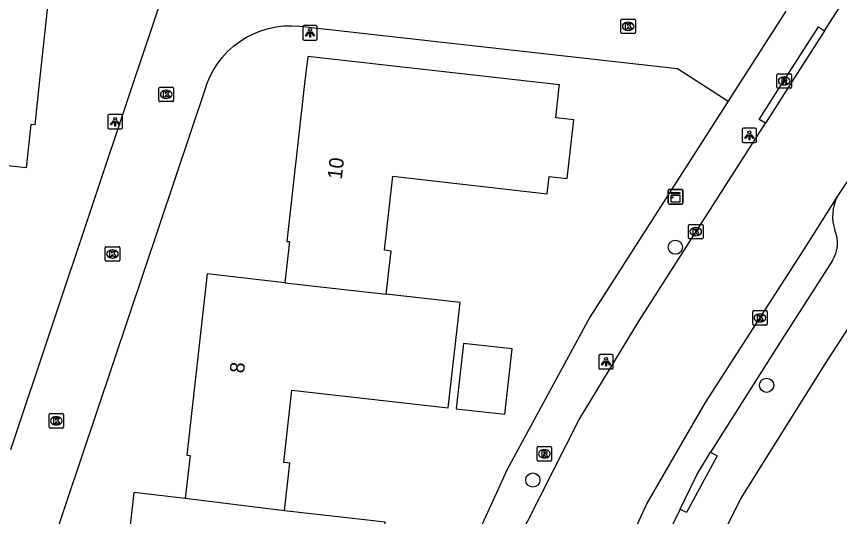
# Model space of a CAD drawing. Extents: x 162398 to 163643, y 386453 to 387397.
# Drawn here: x 162713.1 to 162769.7, y 386720.4 to 386754.8 of the extents above; entities that cross this region are included whole.
import ezdxf

# ---------------------------------------------------------------- set-up
doc = ezdxf.new("R2010")
doc.units = 0
for name, color, linetype in [('IMGEO_Boom', 7, 'Continuous'), ('IMGEO_Kast', 7, 'Continuous'), ('IMGEO_Kolk', 7, 'Continuous'), ('IMGEO_Lichtpunt', 7, 'Continuous'), ('IMGEO_Pand', 7, 'Continuous'), ('IMGEO_Pand_nummerreeks', 7, 'Continuous'), ('IMGEO_Rijbaan_lokaal_open', 7, 'Continuous'), ('IMGEO_Rioolput', 7, 'Continuous'), ('IMGEO_Voetpad_open', 7, 'Continuous')]:
    doc.layers.add(name, color=color, linetype=linetype)

msp = doc.modelspace()

# ---------------------------------------------------------------- linework, layer by layer
at = {"layer": 'IMGEO_Boom'}
for centre in [(162758.414, 386738.944), (162764.691, 386729.444), (162748.609, 386722.92)]:
    msp.add_circle(centre, 0.489, dxfattribs=at)
at = {"layer": 'IMGEO_Kast'}
for p, q in [((162757.926, 386741.989), (162757.926, 386742.83)), ((162757.926, 386742.83), (162757.926, 386741.989)), ((162758.001, 386742.914), (162758.842, 386742.914)), ((162758.842, 386742.914), (162758.001, 386742.914)), ((162758.926, 386742.839), (162758.926, 386741.998)), ((162758.926, 386741.998), (162758.926, 386742.839)), ((162758.851, 386741.914), (162758.01, 386741.914)), ((162758.01, 386741.914), (162758.851, 386741.914))]:
    msp.add_line(p, q, dxfattribs=at)
for points in [[(162758.121, 386742.704), (162758.721, 386742.704), (162758.721, 386742.619), (162758.121, 386742.619), (162758.121, 386742.704)], [(162758.121, 386742.529), (162758.721, 386742.529), (162758.721, 386742.04), (162758.121, 386742.04), (162758.121, 386742.529)]]:
    msp.add_lwpolyline(points, dxfattribs=at)
msp.add_circle((162758.205, 386742.378), 0.0377, dxfattribs=at)
for centre, start, end in [((162758.004, 386742.836), 92.4484, 184.2845), ((162758.004, 386742.836), 92.4484, 184.2845), ((162758.848, 386742.836), 2.4484, 94.2845), ((162758.848, 386742.836), 2.4484, 94.2845), ((162758.004, 386741.992), 182.4484, 274.2845), ((162758.004, 386741.992), 182.4484, 274.2845), ((162758.848, 386741.992), 272.4484, 4.2845), ((162758.848, 386741.992), 272.4484, 4.2845)]:
    msp.add_arc(centre, 0.0779, start, end, dxfattribs=at)
at = {"layer": 'IMGEO_Kolk'}
for p, q in [((162754.669, 386753.716), (162754.669, 386754.568)), ((162754.744, 386754.642), (162755.596, 386754.642)), ((162755.157, 386754.422), (162755.182, 386754.422)), ((162755.67, 386754.568), (162755.67, 386753.716)), ((162755.18, 386753.862), (162755.155, 386753.862)), ((162755.596, 386753.642), (162754.744, 386753.642)), ((162722.894, 386749.034), (162722.894, 386749.886)), ((162722.969, 386749.96), (162723.821, 386749.96)), ((162723.895, 386749.886), (162723.895, 386749.034)), ((162723.382, 386749.74), (162723.407, 386749.74)), ((162723.821, 386748.96), (162722.969, 386748.96)), ((162723.405, 386749.18), (162723.38, 386749.18)), ((162759.317, 386739.588), (162759.317, 386740.44)), ((162759.392, 386740.514), (162760.244, 386740.514)), ((162759.805, 386740.294), (162759.83, 386740.294)), ((162760.318, 386740.44), (162760.318, 386739.588)), ((162759.828, 386739.734), (162759.803, 386739.734)), ((162760.244, 386739.514), (162759.392, 386739.514)), ((162719.193, 386738.055), (162719.193, 386738.907)), ((162719.268, 386738.981), (162720.12, 386738.981)), ((162719.681, 386738.761), (162719.706, 386738.761)), ((162720.194, 386738.907), (162720.194, 386738.055)), ((162720.12, 386737.981), (162719.268, 386737.981)), ((162719.704, 386738.201), (162719.679, 386738.201)), ((162763.733, 386733.652), (162763.733, 386734.504)), ((162763.808, 386734.578), (162764.66, 386734.578)), ((162764.734, 386734.504), (162764.734, 386733.652)), ((162764.221, 386734.358), (162764.246, 386734.358)), ((162764.66, 386733.578), (162763.808, 386733.578)), ((162764.244, 386733.798), (162764.219, 386733.798)), ((162715.331, 386726.571), (162715.331, 386727.423)), ((162715.406, 386727.497), (162716.258, 386727.497)), ((162715.819, 386727.277), (162715.844, 386727.277)), ((162716.332, 386727.423), (162716.332, 386726.571)), ((162715.842, 386726.717), (162715.817, 386726.717)), ((162716.258, 386726.497), (162715.406, 386726.497))]:
    msp.add_line(p, q, dxfattribs=at)
for points in [[(162754.669, 386753.716), (162754.669, 386754.568)], [(162754.744, 386754.642), (162755.596, 386754.642)], [(162754.99, 386754.342), (162755.113, 386754.342), (162755.113, 386754.191), (162755.243, 386754.342), (162755.407, 386754.342), (162755.261, 386754.191), (162755.414, 386753.942), (162755.262, 386753.942), (162755.177, 386754.106), (162755.113, 386754.039), (162755.113, 386753.942), (162754.99, 386753.942), (162754.99, 386754.342)], [(162755.67, 386754.568), (162755.67, 386753.716)], [(162755.596, 386753.642), (162754.744, 386753.642)], [(162722.894, 386749.034), (162722.894, 386749.886)], [(162722.969, 386749.96), (162723.821, 386749.96)], [(162723.895, 386749.886), (162723.895, 386749.034)], [(162723.215, 386749.66), (162723.338, 386749.66), (162723.338, 386749.509), (162723.468, 386749.66), (162723.632, 386749.66), (162723.486, 386749.509), (162723.639, 386749.26), (162723.487, 386749.26), (162723.402, 386749.424), (162723.338, 386749.357), (162723.338, 386749.26), (162723.215, 386749.26), (162723.215, 386749.66)], [(162723.821, 386748.96), (162722.969, 386748.96)], [(162759.317, 386739.588), (162759.317, 386740.44)], [(162759.392, 386740.514), (162760.244, 386740.514)], [(162759.638, 386740.214), (162759.761, 386740.214), (162759.761, 386740.063), (162759.891, 386740.214), (162760.055, 386740.214), (162759.909, 386740.063), (162760.062, 386739.814), (162759.91, 386739.814), (162759.825, 386739.978), (162759.761, 386739.911), (162759.761, 386739.814), (162759.638, 386739.814), (162759.638, 386740.214)], [(162760.318, 386740.44), (162760.318, 386739.588)], [(162760.244, 386739.514), (162759.392, 386739.514)], [(162719.193, 386738.055), (162719.193, 386738.907)], [(162719.268, 386738.981), (162720.12, 386738.981)], [(162719.514, 386738.681), (162719.637, 386738.681), (162719.637, 386738.53), (162719.767, 386738.681), (162719.931, 386738.681), (162719.785, 386738.53), (162719.938, 386738.281), (162719.786, 386738.281), (162719.701, 386738.445), (162719.637, 386738.378), (162719.637, 386738.281), (162719.514, 386738.281), (162719.514, 386738.681)], [(162720.194, 386738.907), (162720.194, 386738.055)], [(162720.12, 386737.981), (162719.268, 386737.981)], [(162763.733, 386733.652), (162763.733, 386734.504)], [(162763.808, 386734.578), (162764.66, 386734.578)], [(162764.734, 386734.504), (162764.734, 386733.652)], [(162764.054, 386734.278), (162764.177, 386734.278), (162764.177, 386734.127), (162764.307, 386734.278), (162764.471, 386734.278), (162764.325, 386734.127), (162764.478, 386733.878), (162764.326, 386733.878), (162764.241, 386734.042), (162764.177, 386733.975), (162764.177, 386733.878), (162764.054, 386733.878), (162764.054, 386734.278)], [(162764.66, 386733.578), (162763.808, 386733.578)], [(162715.331, 386726.571), (162715.331, 386727.423)], [(162715.406, 386727.497), (162716.258, 386727.497)], [(162715.652, 386727.197), (162715.775, 386727.197), (162715.775, 386727.046), (162715.905, 386727.197), (162716.069, 386727.197), (162715.923, 386727.046), (162716.076, 386726.797), (162715.924, 386726.797), (162715.839, 386726.961), (162715.775, 386726.894), (162715.775, 386726.797), (162715.652, 386726.797), (162715.652, 386727.197)], [(162716.332, 386727.423), (162716.332, 386726.571)], [(162716.258, 386726.497), (162715.406, 386726.497)]]:
    msp.add_lwpolyline(points, dxfattribs=at)
for centre, start, end in [((162754.746, 386754.566), 91.552, 178.448), ((162754.746, 386754.566), 91.552, 178.448), ((162755.594, 386754.566), 1.552, 88.448), ((162755.594, 386754.566), 1.552, 88.448), ((162754.746, 386753.718), 181.552, 268.448), ((162754.746, 386753.718), 181.552, 268.448), ((162755.594, 386753.718), 271.552, 358.448), ((162755.594, 386753.718), 271.552, 358.448), ((162722.971, 386749.884), 91.552, 178.448), ((162722.971, 386749.884), 91.552, 178.448), ((162723.819, 386749.884), 1.552, 88.448), ((162723.819, 386749.884), 1.552, 88.448), ((162722.971, 386749.036), 181.552, 268.448), ((162722.971, 386749.036), 181.552, 268.448), ((162723.819, 386749.036), 271.552, 358.448), ((162723.819, 386749.036), 271.552, 358.448), ((162759.394, 386740.438), 91.552, 178.448), ((162759.394, 386740.438), 91.552, 178.448), ((162760.242, 386740.438), 1.552, 88.448), ((162760.242, 386740.438), 1.552, 88.448), ((162759.394, 386739.59), 181.552, 268.448), ((162759.394, 386739.59), 181.552, 268.448), ((162760.242, 386739.59), 271.552, 358.448), ((162760.242, 386739.59), 271.552, 358.448), ((162719.27, 386738.905), 91.552, 178.448), ((162719.27, 386738.905), 91.552, 178.448), ((162720.118, 386738.905), 1.552, 88.448), ((162720.118, 386738.905), 1.552, 88.448), ((162719.27, 386738.057), 181.552, 268.448), ((162719.27, 386738.057), 181.552, 268.448), ((162720.118, 386738.057), 271.552, 358.448), ((162720.118, 386738.057), 271.552, 358.448), ((162763.81, 386734.502), 91.552, 178.448), ((162763.81, 386734.502), 91.552, 178.448), ((162764.658, 386734.502), 1.552, 88.448), ((162764.658, 386734.502), 1.552, 88.448), ((162763.81, 386733.654), 181.552, 268.448), ((162763.81, 386733.654), 181.552, 268.448), ((162764.658, 386733.654), 271.552, 358.448), ((162764.658, 386733.654), 271.552, 358.448), ((162715.408, 386727.421), 91.552, 178.448), ((162715.408, 386727.421), 91.552, 178.448), ((162716.256, 386727.421), 1.552, 88.448), ((162716.256, 386727.421), 1.552, 88.448), ((162715.408, 386726.573), 181.552, 268.448), ((162715.408, 386726.573), 181.552, 268.448), ((162716.256, 386726.573), 271.552, 358.448), ((162716.256, 386726.573), 271.552, 358.448)]:
    msp.add_arc(centre, 0.0765, start, end, dxfattribs=at)
for centre, major_axis, ratio, start_param, end_param in [((162755.156, 386754.142), (-0.387, 0.002), 0.722429, 4.712389, 7.853982), ((162755.181, 386754.142), (-0.39, 0.002), 0.717154, 1.570796, 4.712389), ((162723.381, 386749.46), (-0.387, 0.002), 0.722429, 4.712389, 7.853982), ((162723.406, 386749.46), (-0.39, 0.002), 0.717154, 1.570796, 4.712389), ((162759.804, 386740.014), (-0.387, 0.002), 0.722429, 4.712389, 7.853982), ((162759.829, 386740.014), (-0.39, 0.002), 0.717154, 1.570796, 4.712389), ((162719.68, 386738.481), (-0.387, 0.002), 0.722429, 4.712389, 7.853982), ((162719.705, 386738.481), (-0.39, 0.002), 0.717154, 1.570796, 4.712389), ((162764.22, 386734.078), (-0.387, 0.002), 0.722429, 4.712389, 7.853982), ((162764.245, 386734.078), (-0.39, 0.002), 0.717154, 1.570796, 4.712389), ((162715.818, 386726.997), (-0.387, 0.002), 0.722429, 4.712389, 7.853982), ((162715.843, 386726.997), (-0.39, 0.002), 0.717154, 1.570796, 4.712389)]:
    msp.add_ellipse(centre, major_axis=major_axis, ratio=ratio, start_param=start_param, end_param=end_param, dxfattribs=at)
at = {"layer": 'IMGEO_Lichtpunt'}
for p, q in [((162732.788, 386754.096), (162732.788, 386753.289)), ((162732.788, 386754.096), (162732.788, 386753.289)), ((162733.69, 386754.191), (162732.882, 386754.191)), ((162733.69, 386754.191), (162732.882, 386754.191)), ((162733.784, 386753.289), (162733.784, 386754.096)), ((162733.784, 386753.289), (162733.784, 386754.096)), ((162732.882, 386753.195), (162733.69, 386753.195)), ((162732.882, 386753.195), (162733.69, 386753.195)), ((162720.284, 386748.077), (162719.476, 386748.077)), ((162720.284, 386748.077), (162719.476, 386748.077)), ((162719.382, 386747.982), (162719.382, 386747.175)), ((162719.382, 386747.982), (162719.382, 386747.175)), ((162720.378, 386747.175), (162720.378, 386747.982)), ((162720.378, 386747.175), (162720.378, 386747.982)), ((162719.476, 386747.081), (162720.284, 386747.081)), ((162719.476, 386747.081), (162720.284, 386747.081)), ((162763.004, 386747.044), (162763.004, 386746.237)), ((162763.004, 386747.044), (162763.004, 386746.237)), ((162763.906, 386747.139), (162763.098, 386747.139)), ((162763.906, 386747.139), (162763.098, 386747.139)), ((162764, 386746.237), (162764, 386747.044)), ((162764, 386746.237), (162764, 386747.044)), ((162763.098, 386746.143), (162763.906, 386746.143)), ((162763.098, 386746.143), (162763.906, 386746.143)), ((162753.145, 386731.465), (162753.145, 386730.658)), ((162753.145, 386731.465), (162753.145, 386730.658)), ((162754.047, 386731.56), (162753.239, 386731.56)), ((162754.047, 386731.56), (162753.239, 386731.56)), ((162754.141, 386730.658), (162754.141, 386731.465)), ((162754.141, 386730.658), (162754.141, 386731.465)), ((162753.239, 386730.564), (162754.047, 386730.564)), ((162753.239, 386730.564), (162754.047, 386730.564))]:
    msp.add_line(p, q, dxfattribs=at)
for points in [[(162733.162, 386753.76), (162733.201, 386753.732), (162733.013, 386753.47), (162732.975, 386753.497), (162733.162, 386753.76)], [(162733.374, 386753.732), (162733.412, 386753.759), (162733.599, 386753.497), (162733.56, 386753.469), (162733.374, 386753.732)], [(162733.264, 386753.712), (162733.311, 386753.712), (162733.311, 386753.39), (162733.264, 386753.39), (162733.264, 386753.712)], [(162719.756, 386747.646), (162719.795, 386747.618), (162719.607, 386747.356), (162719.569, 386747.383), (162719.756, 386747.646)], [(162719.858, 386747.598), (162719.905, 386747.598), (162719.905, 386747.276), (162719.858, 386747.276), (162719.858, 386747.598)], [(162719.968, 386747.618), (162720.006, 386747.645), (162720.193, 386747.383), (162720.154, 386747.355), (162719.968, 386747.618)], [(162763.378, 386746.708), (162763.417, 386746.68), (162763.229, 386746.418), (162763.191, 386746.445), (162763.378, 386746.708)], [(162763.48, 386746.66), (162763.527, 386746.66), (162763.527, 386746.338), (162763.48, 386746.338), (162763.48, 386746.66)], [(162763.59, 386746.68), (162763.628, 386746.707), (162763.815, 386746.445), (162763.776, 386746.417), (162763.59, 386746.68)], [(162753.519, 386731.129), (162753.558, 386731.101), (162753.37, 386730.839), (162753.332, 386730.866), (162753.519, 386731.129)], [(162753.731, 386731.101), (162753.769, 386731.128), (162753.956, 386730.866), (162753.917, 386730.838), (162753.731, 386731.101)], [(162753.621, 386731.081), (162753.668, 386731.081), (162753.668, 386730.759), (162753.621, 386730.759), (162753.621, 386731.081)]]:
    msp.add_lwpolyline(points, dxfattribs=at)
for centre in [(162733.287, 386753.894), (162719.881, 386747.78), (162763.503, 386746.842), (162753.644, 386731.263)]:
    msp.add_circle(centre, 0.0994, dxfattribs=at)
for centre, start, end in [((162732.882, 386754.096), 90, 180), ((162732.882, 386754.096), 90, 180), ((162733.69, 386754.096), 0, 90), ((162733.69, 386754.096), 0, 90), ((162732.882, 386753.289), 180, 270), ((162732.882, 386753.289), 180, 270), ((162733.69, 386753.289), 270, 0), ((162733.69, 386753.289), 270, 360), ((162719.476, 386747.982), 90, 180), ((162719.476, 386747.982), 90, 180), ((162720.284, 386747.982), 0, 90), ((162720.284, 386747.982), 0, 90), ((162719.476, 386747.175), 180, 270), ((162719.476, 386747.175), 180, 270), ((162720.284, 386747.175), 270, 0), ((162720.284, 386747.175), 270, 360), ((162763.098, 386747.044), 90, 180), ((162763.098, 386747.044), 90, 180), ((162763.906, 386747.044), 0, 90), ((162763.906, 386747.044), 0, 90), ((162763.098, 386746.237), 180, 270), ((162763.098, 386746.237), 180, 270), ((162763.906, 386746.237), 270, 0), ((162763.906, 386746.237), 270, 360), ((162753.239, 386731.465), 90, 180), ((162753.239, 386731.465), 90, 180), ((162754.047, 386731.465), 0, 90), ((162754.047, 386731.465), 0, 90), ((162753.239, 386730.658), 180, 270), ((162753.239, 386730.658), 180, 270), ((162754.047, 386730.658), 270, 0), ((162754.047, 386730.658), 270, 360)]:
    msp.add_arc(centre, 0.0946, start, end, dxfattribs=at)
at = {"layer": 'IMGEO_Pand'}
for points in [[(162715.694, 386759.778), (162714.638, 386750), (162714.352, 386747.357), (162714.084, 386747.386), (162713.763, 386744.408), (162710.569, 386744.753)], [(162738.531, 386735.719), (162738.865, 386738.683), (162738.398, 386738.736), (162738.971, 386743.824), (162749.594, 386742.626), (162749.727, 386743.807), (162750.979, 386743.666), (162751.435, 386747.704), (162750.183, 386747.845), (162750.426, 386750), (162750.438, 386750.108), (162733.123, 386752.06), (162732.891, 386750), (162731.689, 386739.346), (162731.863, 386739.326), (162731.545, 386736.504)], [(162731.545, 386736.504), (162726.213, 386737.105), (162724.807, 386724.644), (162725.03, 386724.619), (162724.697, 386721.66)], [(162731.545, 386736.504), (162738.531, 386735.719)], [(162731.518, 386720.806), (162731.888, 386724.09), (162731.473, 386724.137), (162732.033, 386729.101), (162742.79, 386727.888), (162743.609, 386735.146), (162738.531, 386735.719)], [(162743.338, 386727.825), (162746.678, 386727.448), (162747.186, 386731.947), (162743.845, 386732.324), (162743.338, 386727.825)], [(162724.697, 386721.66), (162721.171, 386722.057), (162719.763, 386709.572), (162719.989, 386709.546), (162719.653, 386706.562)], [(162731.518, 386720.806), (162724.697, 386721.66)], [(162738.2, 386717.839), (162738.446, 386720.025), (162731.518, 386720.806)]]:
    msp.add_lwpolyline(points, dxfattribs=at)
at = {"layer": 'IMGEO_Rijbaan_lokaal_open'}
for points in [[(162768.682, 386753.831), (162820.766, 386835.256), (162822.004, 386837.173), (162822.433, 386837.832)], [(162712.707, 386725.029), (162721.053, 386750), (162723.976, 386758.744), (162722.022, 386759.421), (162723.941, 386776.08), (162736.827, 386774.61), (162747.949, 386791.857), (162748.421, 386792.667), (162748.819, 386793.516), (162749.139, 386794.397), (162749.38, 386795.303), (162749.538, 386796.228), (162749.557, 386796.385), (162751.861, 386817.275), (162749.46, 386818.878), (162750.034, 386824.476)], [(162766.009, 386755.197), (162762.683, 386750), (162762.044, 386749.001)], [(162710.091, 386702.248), (162726.132, 386750), (162726.172, 386750.119), (162726.376, 386750.623), (162726.624, 386751.108), (162726.914, 386751.568), (162727.244, 386752.001), (162727.611, 386752.402), (162728.013, 386752.769), (162728.446, 386753.099), (162728.907, 386753.389), (162729.392, 386753.636), (162729.896, 386753.839), (162730.417, 386753.996), (162730.95, 386754.106), (162731.491, 386754.168), (162732.035, 386754.181), (162732.578, 386754.146), (162758.569, 386751.236), (162760.491, 386750), (162762.044, 386749.001)], [(162768.682, 386753.831), (162766.226, 386750), (162764.605, 386747.471)], [(162730.673, 386670.035), (162730.769, 386670.321), (162740.68, 386699.903), (162741.907, 386703.446), (162745.663, 386714.324), (162747.378, 386718.341), (162751.779, 386727.044), (162755.937, 386733.921), (162764.605, 386747.471)], [(162769.561, 386742.426), (162771.413, 386745.192)], [(162739.403, 386674.014), (162747.82, 386699.195), (162752.818, 386713.374), (162756.44, 386721.247), (162760.497, 386728.254), (162767.447, 386739.091), (162769.561, 386742.426)]]:
    msp.add_lwpolyline(points, dxfattribs=at)
at = {"layer": 'IMGEO_Rioolput'}
for p, q in [((162765.4, 386749.956), (162765.4, 386750.808)), ((162765.475, 386750.882), (162766.327, 386750.882)), ((162765.888, 386750.662), (162765.913, 386750.662)), ((162766.401, 386750.808), (162766.401, 386749.956)), ((162766.327, 386749.882), (162765.475, 386749.882)), ((162765.911, 386750.102), (162765.886, 386750.102)), ((162748.902, 386724.301), (162748.902, 386725.153)), ((162748.977, 386725.227), (162749.829, 386725.227)), ((162749.39, 386725.007), (162749.415, 386725.007)), ((162749.903, 386725.153), (162749.903, 386724.301)), ((162749.413, 386724.447), (162749.388, 386724.447)), ((162749.829, 386724.227), (162748.977, 386724.227))]:
    msp.add_line(p, q, dxfattribs=at)
for points in [[(162765.4, 386749.956), (162765.4, 386750.808)], [(162765.475, 386750.882), (162766.327, 386750.882)], [(162765.989, 386750.58), (162765.737, 386750.582), (162765.737, 386750.182)], [(162765.737, 386750.182), (162765.861, 386750.182), (162765.861, 386750.344), (162765.872, 386750.344)], [(162765.915, 386750.501), (162765.861, 386750.501), (162765.861, 386750.42)], [(162765.861, 386750.42), (162765.913, 386750.42)], [(162766.401, 386750.808), (162766.401, 386749.956)], [(162766.327, 386749.882), (162765.475, 386749.882)], [(162765.919, 386750.315), (162765.99, 386750.182), (162766.13, 386750.182), (162766.065, 386750.308)], [(162748.902, 386724.301), (162748.902, 386725.153)], [(162748.977, 386725.227), (162749.829, 386725.227)], [(162749.491, 386724.925), (162749.239, 386724.927), (162749.239, 386724.527)], [(162749.903, 386725.153), (162749.903, 386724.301)], [(162749.239, 386724.527), (162749.363, 386724.527), (162749.363, 386724.689), (162749.374, 386724.689)], [(162749.417, 386724.846), (162749.363, 386724.846), (162749.363, 386724.765)], [(162749.363, 386724.765), (162749.415, 386724.765)], [(162749.421, 386724.66), (162749.492, 386724.527), (162749.632, 386724.527), (162749.567, 386724.653)], [(162749.829, 386724.227), (162748.977, 386724.227)]]:
    msp.add_lwpolyline(points, dxfattribs=at)
for centre, radius, start, end in [((162765.477, 386750.806), 0.0765, 91.552, 178.448), ((162765.477, 386750.806), 0.0765, 91.552, 178.448), ((162765.871, 386750.291), 0.0533, 26.0293, 88.6989), ((162765.897, 386750.609), 0.19, 274.7715, 282.9687), ((162765.921, 386750.405), 0.0964, 77.0061, 93.1865), ((162765.935, 386750.462), 0.0378, 276.6634, 79.6772), ((162765.988, 386750.47), 0.109, 350.3612, 89.416), ((162765.986, 386750.47), 0.112, 277.5842, 350.9817), ((162765.97, 386750.255), 0.108, 29.5134, 73.7905), ((162766.325, 386750.806), 0.0765, 1.552, 88.448), ((162766.325, 386750.806), 0.0765, 1.552, 88.448), ((162765.477, 386749.958), 0.0765, 181.552, 268.448), ((162765.477, 386749.958), 0.0765, 181.552, 268.448), ((162766.325, 386749.958), 0.0765, 271.552, 358.448), ((162766.325, 386749.958), 0.0765, 271.552, 358.448), ((162748.979, 386725.151), 0.0765, 91.552, 178.448), ((162748.979, 386725.151), 0.0765, 91.552, 178.448), ((162749.49, 386724.815), 0.109, 350.3612, 89.416), ((162749.827, 386725.151), 0.0765, 1.552, 88.448), ((162749.827, 386725.151), 0.0765, 1.552, 88.448), ((162748.979, 386724.303), 0.0765, 181.552, 268.448), ((162748.979, 386724.303), 0.0765, 181.552, 268.448), ((162749.373, 386724.636), 0.0533, 26.0293, 88.6989), ((162749.399, 386724.954), 0.19, 274.7715, 282.9687), ((162749.423, 386724.75), 0.0964, 77.0061, 93.1865), ((162749.437, 386724.807), 0.0378, 276.6634, 79.6772), ((162749.488, 386724.815), 0.112, 277.5842, 350.9817), ((162749.472, 386724.6), 0.108, 29.5134, 73.7905), ((162749.827, 386724.303), 0.0765, 271.552, 358.448), ((162749.827, 386724.303), 0.0765, 271.552, 358.448)]:
    msp.add_arc(centre, radius, start, end, dxfattribs=at)
for centre, major_axis, ratio, start_param, end_param in [((162765.887, 386750.382), (-0.387, 0.002), 0.722429, 4.712389, 7.853982), ((162765.912, 386750.382), (-0.39, 0.002), 0.717154, 1.570796, 4.712389), ((162749.389, 386724.727), (-0.387, 0.002), 0.722429, 4.712389, 7.853982), ((162749.414, 386724.727), (-0.39, 0.002), 0.717154, 1.570796, 4.712389)]:
    msp.add_ellipse(centre, major_axis=major_axis, ratio=ratio, start_param=start_param, end_param=end_param, dxfattribs=at)
at = {"layer": 'IMGEO_Voetpad_open'}
for points in [[(162764.605, 386747.471), (162764.184, 386747.74), (162765.63, 386750), (162768.256, 386754.104), (162768.682, 386753.831)], [(162762.044, 386749.001), (162752.537, 386734.127), (162746.835, 386723.64), (162744.257, 386717.994), (162741.576, 386711.487), (162727.566, 386670.164)], [(162744.409, 386671.894), (162754.454, 386701.785), (162757.742, 386711.279), (162762.934, 386721.672), (162768.744, 386730.951), (162776.93, 386743.582)], [(162769.217, 386738.029), (162765.954, 386732.907), (162760.841, 386724.833)], [(162760.841, 386724.833), (162761.28, 386724.597), (162759.183, 386720.695), (162758.738, 386720.921)], [(162758.738, 386720.921), (162759.898, 386723.289), (162760.841, 386724.833)], [(162758.738, 386720.921), (162754.722, 386712.724), (162753.698, 386709.944)]]:
    msp.add_lwpolyline(points, dxfattribs=at)
for centre, radius, start, end in [((162772.166, 386741.07), 2.937, 152.4987, 199.1123), ((162767.313, 386739.235), 2.254, 327.6483, 22.7833)]:
    msp.add_arc(centre, radius, start, end, dxfattribs=at)

# ---------------------------------------------------------------- texts
at = {"layer": 'IMGEO_Pand_nummerreeks'}
for s, rotation, p in [('10', 83.563, (162735.468, 386743.578)), ('8', 83.5624, (162728.739, 386730.236))]:
    msp.add_text(s, height=1, rotation=rotation, dxfattribs=at).set_placement(p)

doc.saveas('drawing.dxf')
